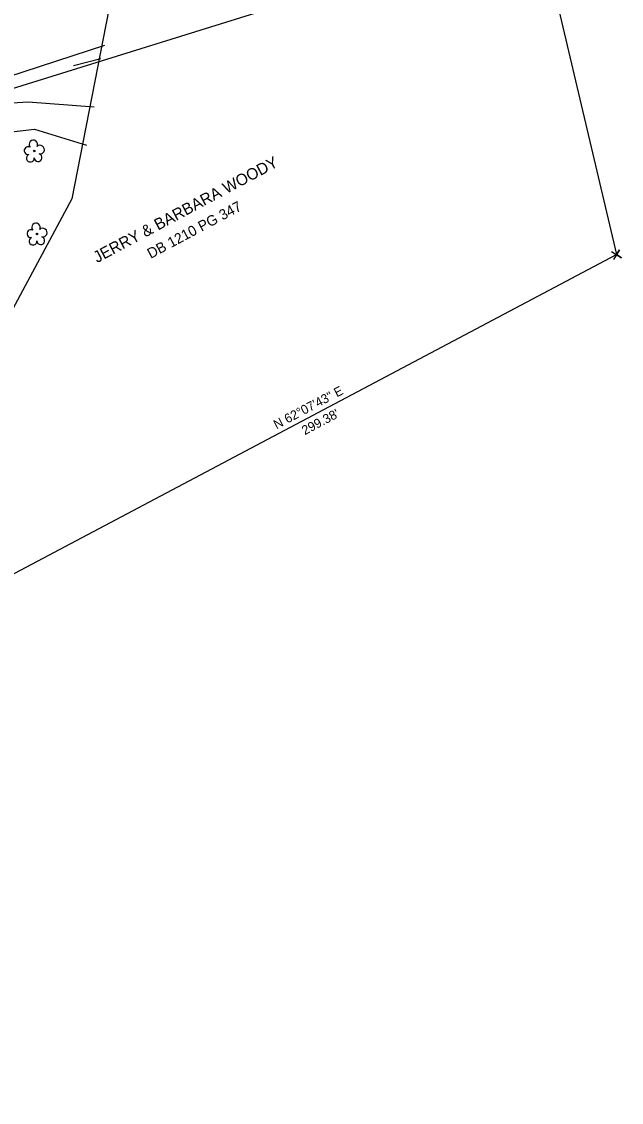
# Model space of a CAD drawing. Extents: x 1380524 to 1382335, y 594765 to 596944.
# Drawn here: x 1382074 to 1382335.3, y 595253.4 to 595723.8 of the extents above; entities that cross this region are included whole.
import ezdxf

# ---------------------------------------------------------------- set-up
doc = ezdxf.new("R2010")
doc.units = 0
for name, color, linetype in [('Exist Other Culture Fence Line Text', 7, 'Continuous'), ('Exist Right of Way Line', 7, 'Continuous'), ('Exist Roads EOP Other', 7, 'Continuous'), ('Exist Structure Major Bridge WW', 7, 'Continuous'), ('Exist Structure Minor Pipes CMP 18 Inch', 7, 'Continuous'), ('Exist Utilities Power Tower Text', 7, 'Continuous'), ('Prop Drainage Structure Box Number Symbol CELL', 7, 'Continuous'), ('Prop Earthen Structure Cut Ditch Special Detail Label', 7, 'Continuous'), ('Prop Earthen Structure V Ditch Lateral Detail Label', 7, 'Continuous'), ('Prop Erosion Rip Rap At Embankment Detail CELL', 7, 'Continuous')]:
    doc.layers.add(name, color=color, linetype=linetype)

# ---------------------------------------------------------------- blocks, each defined once
blk = doc.blocks.new('EXIST VEGETATION TREE')
at = {"layer": 'Prop Erosion Rip Rap At Embankment Detail CELL'}
blk.add_line((0, 0), (0, 0), dxfattribs=at)
blk.add_circle((0, 0), 0.00652, dxfattribs=at)
for centre, radius, start, end in [((-0.0077, 0.0575), 0.0371, 330.16508, 219.71335), ((-0.0521, 0.0031), 0.0345, 62.66361, 279.3457), ((0.051, 0.0118), 0.038, 257.1011, 134.19993), ((-0.0341, -0.0624), 0.0338, 111.56708, 6.23104), ((0.0335, -0.058), 0.034, 181.28216, 74.55999)]:
    blk.add_arc(centre, radius, start, end, dxfattribs=at)

msp = doc.modelspace()

# ---------------------------------------------------------------- linework, layer by layer
at = {"layer": 'Exist Roads EOP Other'}
for points in [[(1382105.64, 595686.55), (1382076.86, 595688.73), (1382055.65, 595687.52), (1382013.67, 595678.93), (1381981.76, 595668.62), (1381934.99, 595653.84), (1381898.93, 595644.26), (1381885.04, 595644.78), (1381879.57, 595650.76), (1381878.26, 595659.39)], [(1381899.37, 595634.27), (1381938.06, 595644.53), (1381993.1, 595661.21), (1382020.12, 595666.97), (1382058.22, 595674.5), (1382079.57, 595676.98), (1382102.22, 595669.97)]]:
    msp.add_lwpolyline(points, dxfattribs=at)
at = {"layer": 'Exist Structure Major Bridge WW'}
msp.add_line((1382333.18, 595622.39), (1382333.18, 595622.39), dxfattribs=at)
msp.add_lwpolyline([(1382331.05, 595623.7), (1382335.3, 595621.07), (1382333.18, 595622.39), (1382334.49, 595624.51), (1382331.86, 595620.26)], dxfattribs=at)
at = {"layer": 'Exist Utilities Power Tower Text'}
for p, q in [((1382255.74, 595951.12), (1382333.18, 595622.39)), ((1381879.85, 595635.61), (1382234.24, 595745.79)), ((1382068.52, 595482.43), (1382333.18, 595622.39))]:
    msp.add_line(p, q, dxfattribs=at)
at = {"layer": 'Prop Drainage Structure Box Number Symbol CELL'}
msp.add_lwpolyline([(1382083.62, 595964.41), (1382120.69, 595773.82), (1382095.82, 595646.75), (1382010.85, 595488.75), (1381848.52, 595352.32), (1381617.36, 595239.15), (1381304.92, 595184.07), (1381005.77, 595330.75), (1380937.13, 595525.19), (1380768.47, 595849.39), (1380967, 596250.36)], close=True, dxfattribs=at)
at = {"layer": 'Prop Earthen Structure Cut Ditch Special Detail Label'}
msp.add_lwpolyline([(1382110.04, 595713.45), (1382067.83, 595699.67), (1381990.15, 595678.17), (1381936.17, 595661.06), (1381895.27, 595653.13), (1381895.13, 595667.26), (1381911.22, 595723.52), (1381948.84, 595697.3), (1382012.6, 595721.97), (1382044.15, 595740.68), (1382086.44, 595744.88), (1382118.43, 595781.95)], dxfattribs=at)
at = {"layer": 'Prop Earthen Structure V Ditch Lateral Detail Label'}
msp.add_line((1382096.56, 595704.67), (1382108.51, 595707.74), dxfattribs=at)

# ---------------------------------------------------------------- block references
at = {"layer": 'Prop Erosion Rip Rap At Embankment Detail CELL', "xscale": 50, "yscale": 50}
for p in [(1382079.47, 595667.52), (1382080.65, 595631.38)]:
    msp.add_blockref('EXIST VEGETATION TREE', p, dxfattribs=at)

# ---------------------------------------------------------------- texts
at = {"layer": 'Exist Other Culture Fence Line Text'}
for s, p in [('N 62%%D07\'43" E', (1382185.05, 595546.32)), ("299.38'", (1382197.35, 595543.77))]:
    msp.add_text(s, height=4, rotation=27.8715, dxfattribs=at).set_placement(p)
at = {"layer": 'Exist Right of Way Line'}
msp.add_text('JERRY & BARBARA WOODY', height=5, rotation=28.0936, dxfattribs=at).set_placement((1382106.87, 595618.65))
at = {"layer": 'Exist Structure Minor Pipes CMP 18 Inch'}
msp.add_text('DB 1210 PG 347', height=4.5, rotation=28.0936, dxfattribs=at).set_placement((1382130.22, 595620.52))

doc.saveas('drawing.dxf')
